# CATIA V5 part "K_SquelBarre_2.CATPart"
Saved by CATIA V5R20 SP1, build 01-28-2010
Part number: squelette_barre_2
Publications: "Point.1", "Point.2", "Droite.1", "Plan.1", "Droite.2", "Droite.3"
Bounding box of the stored display mesh (mm): x 0 to 0, y 0 to 20, z 0 to 15
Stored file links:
  G:\Khaled_CFAO_2011\ST2M\ST2M_GR2\gcausse\Khaled\CAD_ThinkMotion\K_SquelBarre_2.CATPart
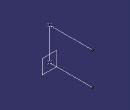
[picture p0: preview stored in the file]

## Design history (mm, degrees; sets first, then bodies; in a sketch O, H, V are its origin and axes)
Set1
  Point1: (0, 0, 0)
  Point2: (0, 0, 15)
  Line1: type PtPt, FirstPoint Point1, SecondPoint Point2
  Plane1: type Offset, RefPlane zx-plane, Offset 0
  Line2: type PtDir, RefPoint Point1, Direction Plane1, Start 0, End 20
  Line3: type PtDir, RefPoint Point2, Direction Plane1, Start 0, End 20
Body1 (main body)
